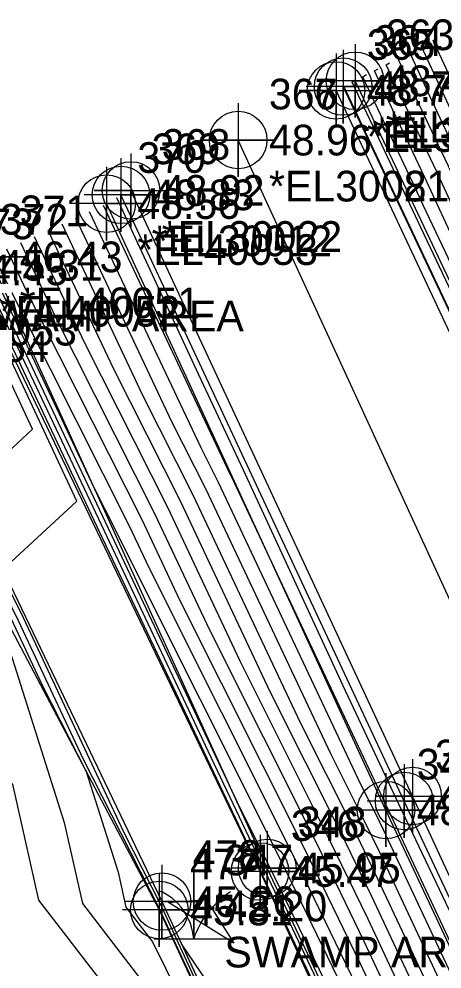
# Model space of a CAD drawing. Extents: x 2090860 to 2091277, y 159470 to 160080.
# Drawn here: x 2090910.5 to 2090944.9, y 159984.2 to 160061.6 of the extents above; entities that cross this region are included whole.
import ezdxf

# ---------------------------------------------------------------- set-up
doc = ezdxf.new("R2010")
doc.units = 0
for name, color, linetype in [('DTM Contours Major', 7, 'Continuous'), ('DTM Contours Minor', 7, 'Continuous'), ('Exist DTM Breakline', 7, 'Continuous'), ('Exist DTM Breakline Cogo Comment', 7, 'Continuous'), ('Exist DTM Breakline Cogo Elevation', 7, 'Continuous'), ('Exist DTM Breakline Cogo Number', 7, 'Continuous'), ('Exist DTM Breakline Cogo Point CELL', 7, 'Continuous'), ('Exist DTM Crownline', 7, 'Continuous'), ('Exist DTM Crownline Cogo Comment', 7, 'Continuous'), ('Exist DTM Crownline Cogo Elevation', 7, 'Continuous'), ('Exist DTM Crownline Cogo Number', 7, 'Continuous'), ('Exist DTM Crownline Cogo Point CELL', 7, 'Continuous'), ('Exist Hydro Swamp or Marsh', 7, 'Continuous'), ('Exist Hydro Swamp or Marsh Cogo Comment', 7, 'Continuous'), ('Exist Hydro Swamp or Marsh Cogo Elevation', 7, 'Continuous'), ('Exist Hydro Swamp or Marsh Cogo Number', 7, 'Continuous'), ('Exist Roads EOP', 7, 'Continuous'), ('Exist Roads EOP Cogo Comment', 7, 'Continuous'), ('Exist Roads EOP Cogo Elevation', 7, 'Continuous'), ('Exist Roads EOP Cogo Number', 7, 'Continuous'), ('Exist Roads EOP Cogo Point CELL', 7, 'Continuous'), ('Exist Roads EOT', 7, 'Continuous'), ('Exist Roads EOT Cogo Comment', 7, 'Continuous'), ('Exist Roads EOT Cogo Elevation', 7, 'Continuous'), ('Exist Roads EOT Cogo Number', 7, 'Continuous'), ('Exist Roads EOT Cogo Point CELL', 7, 'Continuous')]:
    doc.layers.add(name, color=color, linetype=linetype)

msp = doc.modelspace()

# ---------------------------------------------------------------- linework, layer by layer
at = {"layer": 'DTM Contours Major'}
for points in [[(2091021.18, 159890.907), (2091013.639, 159907.174), (2091008.516, 159918.108), (2091005.725, 159924.066), (2091001.855, 159932.408), (2090996.755, 159943.477), (2090989.564, 159959.773), (2090985.428, 159962.142), (2090982.708, 159967.911), (2090974.675, 159984.898), (2090972.744, 159996.202), (2090967.23, 160007.833), (2090960.061, 160023.383), (2090954.323, 160035.484), (2090947.368, 160050.56), (2090945.472, 160054.558), (2090943.253, 160059.365), (2090943.413, 160059.46)], [(2091015.949, 159893.794), (2091005.233, 159916.667), (2090999.394, 159929.129), (2090998.605, 159930.829), (2090988.204, 159953.404), (2090986.126, 159958.114), (2090984.93, 159958.799), (2090981.087, 159966.952), (2090969.734, 159990.958), (2090969.141, 159994.43), (2090958.495, 160016.884), (2090956.34, 160021.56), (2090945.578, 160044.255), (2090943.533, 160048.687), (2090940.07, 160055.988), (2090939.423, 160057.391), (2090939.712, 160057.563)], [(2090915.092, 160045.426), (2090922.919, 160028.827), (2090925.677, 160023.356), (2090935.836, 160001.778), (2090938.587, 159996.284), (2090939.794, 159993.785), (2090945.294, 159982.053), (2090947.597, 159977.284), (2090958.084, 159954.914), (2090958.856, 159953.218), (2090962.481, 159945.429), (2090964.802, 159940.332), (2090975.096, 159918.212), (2090976.136, 159916.102), (2090980.927, 159905.726), (2090983.402, 159900.704)], [(2090910.606, 160043.392), (2090913.448, 160037.366), (2090921.532, 160021.331), (2090926.001, 160011.839), (2090934.731, 159994.403), (2090938.563, 159986.471), (2090941.418, 159980.382), (2090948.738, 159965.223), (2090954.329, 159953.296), (2090956.792, 159947.89), (2090958.683, 159943.825), (2090966.198, 159927.322), (2090971.199, 159916.575), (2090974.729, 159909.419), (2090977.08, 159904.325)], [(2090907.426, 160041.969), (2090911.786, 160032.768), (2090917.984, 160019.602), (2090928.464, 159997.339), (2090930.876, 159992.521), (2090937.332, 159979.157), (2090937.542, 159978.71), (2090949.879, 159953.162), (2090950.574, 159951.679), (2090954.727, 159942.562), (2090954.886, 159942.222), (2090962.638, 159925.196), (2090966.571, 159916.855), (2090967.464, 159914.985), (2090973.015, 159903.605)], [(2090900.828, 160040.593), (2090907.904, 160024.765), (2090911.605, 160028.202), (2090905.415, 160041.412)], [(2090878.864, 160034.967), (2090897.091, 160039.466), (2090903.651, 160025.321), (2090910.038, 160012.34), (2090912.377, 160007.335), (2090915.967, 160000.292), (2090918.562, 159992.105), (2090919.202, 159989.241), (2090921.362, 159986.426), (2090931.819, 159965.183), (2090930.712, 159963.948), (2090932.018, 159960.802), (2090932.724, 159957.106), (2090937.257, 159949.444), (2090930, 159941.72), (2090927.457, 159942.543), (2090920, 159946.378), (2090916.149, 159943.851), (2090910, 159943.546), (2090902.359, 159947.641), (2090900, 159946.671), (2090893.58, 159946.42), (2090892.56, 159944.88)]]:
    msp.add_lwpolyline(points, dxfattribs=at)
at = {"layer": 'DTM Contours Minor'}
for points in [[(2091021.989, 159891.262), (2091013.061, 159910.519), (2091009.337, 159918.469), (2091007.307, 159922.8), (2091002.667, 159932.803), (2090998.893, 159940.995), (2090990.424, 159960.188), (2090985.552, 159962.978), (2090983.114, 159968.151), (2090975.91, 159983.383), (2090973.645, 159996.645), (2090969.414, 160005.57), (2090960.992, 160023.839), (2090956.509, 160033.292), (2090948.326, 160051.028), (2090946.822, 160054.2), (2090944.211, 160059.859), (2090944.338, 160059.934)], [(2091014.217, 159903.829), (2091007.695, 159917.748), (2091004.142, 159925.332), (2091001.042, 159932.013), (2090994.617, 159945.959), (2090988.704, 159959.359), (2090985.303, 159961.306), (2090982.303, 159967.671), (2090973.44, 159986.413), (2090971.844, 159995.759), (2090965.046, 160010.096), (2090959.131, 160022.927), (2090952.137, 160037.677), (2090946.409, 160050.092), (2090944.121, 160054.915), (2090942.296, 160058.872), (2090942.487, 160058.986)], [(2091014.794, 159900.484), (2091006.874, 159917.387), (2091002.559, 159926.597), (2091000.23, 159931.619), (2090992.479, 159948.441), (2090987.845, 159958.944), (2090985.179, 159960.47), (2090981.898, 159967.432), (2090972.204, 159987.928), (2090970.943, 159995.316), (2090962.863, 160012.359), (2090958.2, 160022.472), (2090949.95, 160039.87), (2090945.45, 160049.623), (2090942.771, 160055.273), (2090941.338, 160058.378), (2090941.562, 160058.512)], [(2091015.372, 159897.139), (2091006.054, 159917.027), (2091000.976, 159927.863), (2090999.417, 159931.224), (2090990.342, 159950.923), (2090986.985, 159958.529), (2090985.054, 159959.635), (2090981.492, 159967.192), (2090970.969, 159989.443), (2090970.042, 159994.873), (2090960.679, 160014.622), (2090957.27, 160022.016), (2090947.764, 160042.063), (2090944.492, 160049.155), (2090941.421, 160055.631), (2090940.381, 160057.885), (2090940.637, 160058.037)], [(2091016.527, 159890.449), (2091004.412, 159916.306), (2090997.811, 159930.395), (2090997.792, 159930.434), (2090986.066, 159955.886), (2090985.266, 159957.699), (2090984.806, 159957.963), (2090980.682, 159966.713), (2090968.499, 159992.473), (2090968.24, 159993.988), (2090956.311, 160019.147), (2090955.409, 160021.104), (2090943.391, 160046.448), (2090942.575, 160048.218), (2090938.72, 160056.346), (2090938.465, 160056.898), (2090938.787, 160057.089)], [(2091015.092, 159888.281), (2091005.494, 159908.792), (2091002.253, 159915.399), (2090998.196, 159923.671), (2090995.587, 159929.309), (2090993.655, 159934.254), (2090987.577, 159947.689), (2090983.614, 159956.284), (2090983.391, 159956.773), (2090979.397, 159965.44), (2090979.189, 159965.897), (2090967.415, 159991.324), (2090966.567, 159993.113), (2090960.639, 160005.911), (2090959.796, 160007.69), (2090947.752, 160033.198), (2090947.057, 160034.665), (2090937.109, 160055.735), (2090936.921, 160056.131), (2090936.936, 160056.14)], [(2091009.719, 159902.684), (2091003.488, 159915.918), (2091000.285, 159922.734), (2090996.873, 159929.981), (2090990.78, 159943.197), (2090984.364, 159957.258), (2090983.277, 159959.617), (2090980.176, 159966.423), (2090978.448, 159970.155), (2090967.363, 159993.547), (2090966.269, 159995.909), (2090955.847, 160017.91), (2090953.21, 160023.496), (2090943.221, 160044.585), (2090940.726, 160049.87), (2090937.604, 160056.462), (2090937.861, 160056.615)], [(2090918.443, 160047.072), (2090925.071, 160032.691), (2090928.75, 160024.871), (2090936.833, 160007.361), (2090941.384, 159997.661), (2090946.344, 159987.242), (2090948.128, 159983.436), (2090958.851, 159960.931), (2090960.998, 159956.352), (2090964.881, 159948.099), (2090965.492, 159946.787), (2090977.739, 159920.762), (2090978.261, 159919.644), (2090983.592, 159908.064), (2090984.057, 159907.047), (2090994.33, 159884.723)], [(2090916.214, 160045.934), (2090925.287, 160026.693), (2090926.714, 160023.863), (2090938.295, 159999.263), (2090939.55, 159996.755), (2090940.102, 159995.614), (2090946.263, 159982.47), (2090947.312, 159980.299), (2090959.023, 159955.318), (2090959.373, 159954.55), (2090963.43, 159945.83), (2090964.452, 159943.584), (2090976.07, 159918.621), (2090976.488, 159917.773), (2090981.889, 159906.077), (2090983.02, 159903.782)], [(2090917.335, 160046.443), (2090927.654, 160024.558), (2090927.75, 160024.369), (2090931.7, 160015.979), (2090940.501, 159997.22), (2090941.185, 159995.783), (2090947.222, 159982.907), (2090948.733, 159979.736), (2090959.976, 159955.756), (2090960.546, 159954.544), (2090964.408, 159946.258), (2090966.553, 159941.699), (2090977.104, 159919.081), (2090978.421, 159916.221), (2090982.884, 159906.464), (2090984.288, 159903.411)], [(2090912.849, 160044.409), (2090918.183, 160033.097), (2090923.605, 160022.344), (2090930.919, 160006.809), (2090936.659, 159995.344), (2090939.178, 159990.128), (2090943.356, 159981.217), (2090948.168, 159971.253), (2090956.207, 159954.105), (2090957.824, 159950.554), (2090960.582, 159944.627), (2090965.5, 159933.827), (2090973.148, 159917.393), (2090975.433, 159912.761), (2090979.004, 159905.026)], [(2090913.971, 160044.918), (2090920.551, 160030.962), (2090924.641, 160022.85), (2090933.377, 160004.293), (2090937.623, 159995.814), (2090939.486, 159991.957), (2090944.325, 159981.635), (2090947.882, 159974.268), (2090957.145, 159954.509), (2090958.34, 159951.886), (2090961.531, 159945.028), (2090965.151, 159937.08), (2090974.122, 159917.803), (2090975.785, 159914.432), (2090979.965, 159905.376)], [(2090911.728, 160043.901), (2090915.815, 160035.231), (2090922.569, 160021.838), (2090928.46, 160009.324), (2090935.695, 159994.873), (2090938.871, 159988.3), (2090942.387, 159980.799), (2090948.453, 159968.238), (2090955.268, 159953.701), (2090957.308, 159949.222), (2090959.632, 159944.226), (2090965.849, 159930.575), (2090972.174, 159916.984), (2090975.081, 159911.09), (2090978.042, 159904.675)], [(2090909.485, 160042.884), (2090911.08, 160039.501), (2090920.496, 160020.825), (2090923.543, 160014.354), (2090933.768, 159993.933), (2090938.255, 159984.643), (2090940.449, 159979.964), (2090949.023, 159962.207), (2090953.39, 159952.892), (2090956.276, 159946.558), (2090957.734, 159943.424), (2090966.547, 159924.07), (2090970.225, 159916.166), (2090974.377, 159907.749), (2090976.119, 159903.975)], [(2090907.788, 160042.123), (2090909.613, 160038.271), (2090916.596, 160023.437), (2090918.424, 160019.813), (2090918.625, 160019.385), (2090931.84, 159992.992), (2090937.64, 159980.985), (2090938.511, 159979.128), (2090949.594, 159956.177), (2090951.513, 159952.083), (2090955.244, 159943.894), (2090955.835, 159942.622), (2090967.245, 159917.565), (2090968.277, 159915.347), (2090973.673, 159904.407)], [(2090908.363, 160042.375), (2090908.712, 160041.635), (2090919.46, 160020.319), (2090921.084, 160016.87), (2090932.804, 159993.462), (2090937.948, 159982.814), (2090939.48, 159979.546), (2090949.308, 159959.192), (2090952.452, 159952.487), (2090955.76, 159945.226), (2090956.784, 159943.023), (2090966.896, 159920.817), (2090969.251, 159915.756), (2090974.025, 159906.078), (2090975.157, 159903.624)], [(2090899.563, 160040.331), (2090909.838, 160017.348), (2090915.213, 160022.339), (2090906.225, 160041.521)], [(2090906.701, 160041.663), (2090916.132, 160021.763), (2090917.301, 160019.278), (2090919.911, 160013.734), (2090930.148, 159992.169), (2090935.256, 159981.379), (2090936.616, 159978.521), (2090944.254, 159962.401), (2090949.505, 159951.363), (2090952.287, 159945.521), (2090954.079, 159941.72), (2090957.972, 159933.464), (2090966.981, 159914.593), (2090968.004, 159912.496), (2090972.898, 159902.775)], [(2090907.064, 160041.816), (2090913.959, 160027.266), (2090917.643, 160019.44), (2090925.862, 160001.979), (2090930.45, 159992.315), (2090932.739, 159987.48), (2090936.984, 159978.555), (2090940.085, 159972.01), (2090949.879, 159951.423), (2090950.719, 159949.661), (2090954.36, 159941.937), (2090962.272, 159925.16), (2090967.223, 159914.789), (2090970.51, 159908.05), (2090973.119, 159902.868)], [(2090889.626, 160037.801), (2090897.613, 160039.773), (2090906.696, 160020.187), (2090910.431, 160012.597), (2090915.684, 160001.354), (2090921.934, 159989.091), (2090923.078, 159986.602), (2090934.563, 159961.929)], [(2090898.298, 160040.07), (2090902.561, 160030.534), (2090909.741, 160015.052), (2090910.823, 160012.853), (2090918.991, 159995.373), (2090922.033, 159989.405), (2090928.025, 159976.37), (2090934.637, 159962.164), (2090937.707, 159955.499), (2090940.625, 159949.227), (2090948.523, 159931.794), (2090953.056, 159921.956), (2090965.045, 159895.337)], [(2090918.502, 159981.498), (2090912.109, 159989.826), (2090910, 159999.276), (2090908.566, 160000), (2090909.867, 160000.133), (2090907.218, 160011.584), (2090906.209, 160014.977), (2090900.403, 160029.812), (2090897.561, 160035.589), (2090896.047, 160038.853), (2090870.427, 160032.529), (2090884.177, 160034.776), (2090874.349, 160030), (2090870.467, 160020.467), (2090870.195, 160020), (2090870, 160019.313), (2090862.368, 160017.632), (2090862.193, 160015.615)], [(2090868.102, 160032.133), (2090896.569, 160039.16), (2090900.606, 160030.455), (2090908.186, 160015.051), (2090909.143, 160012.603), (2090909.31, 160012.043), (2090909.771, 160010.051), (2090914.18, 159996.146), (2090915.655, 159989.533), (2090920.643, 159983.036), (2090925.583, 159973.001), (2090921.92, 159968.915), (2090922.513, 159967.487), (2090920, 159968.451), (2090915.329, 159970), (2090910, 159971.335), (2090905.305, 159974.695), (2090900, 159975.694), (2090891.754, 159970), (2090890, 159969.104), (2090886.285, 159967.429), (2090886.339, 159960.983), (2090883.674, 159965.814)], [(2090922.651, 159989.628), (2090925.734, 159989.867), (2090927.977, 159986.319), (2090922.651, 159989.628)], [(2090971.838, 159903.298), (2090965.559, 159913.825), (2090960.005, 159918.329), (2090953.785, 159940.417), (2090952.656, 159942.311), (2090953.018, 159943.141), (2090949.131, 159951.303), (2090948.423, 159952.793), (2090946.196, 159957.493), (2090935.425, 159968.942), (2090923.729, 159986.244), (2090932.971, 159966.138), (2090934.711, 159962.399), (2090939.74, 159951.48), (2090940.783, 159949.239), (2090943.605, 159943.01), (2090953.294, 159921.983), (2090957.425, 159912.812), (2090965.766, 159894.719)]]:
    msp.add_lwpolyline(points, dxfattribs=at)
at = {"layer": 'Exist DTM Breakline'}
for points in [[(2091054.851, 159814.302), (2091016.781, 159888.977), (2090997.773, 159930.425), (2090980.346, 159966.514), (2090937.845, 160056.578)], [(2091012.481, 159842.709), (2090995.611, 159879.293), (2090976.725, 159918.896), (2090959.8, 159955.653), (2090940.36, 159997.15), (2090917.627, 160046.575)], [(2091019.809, 159801.913), (2091004.418, 159836.946), (2090986.475, 159875.987), (2090967.517, 159915.028), (2090950.041, 159951.449), (2090930.695, 159992.433), (2090908.049, 160042.233)], [(2091019.111, 159801.55), (2091003.076, 159836.513), (2090986.016, 159875.809), (2090966.872, 159914.505), (2090949.073, 159951.294), (2090930.109, 159992.15), (2090906.432, 160041.549)], [(2090898.02, 160040.012), (2090922.126, 159989.703), (2090940.871, 159949.246), (2090967.299, 159891.857)], [(2090895.734, 160038.669), (2090921.911, 159989.017), (2090940.353, 159949.207), (2090966.689, 159891.716)]]:
    msp.add_lwpolyline(points, dxfattribs=at)
at = {"layer": 'Exist DTM Breakline Cogo Point CELL'}
for points in [[(2090937.845, 160059.578), (2090937.845, 160053.578), (2090937.845, 160056.578), (2090940.845, 160056.578), (2090934.845, 160056.578)], [(2090917.627, 160049.575), (2090917.627, 160043.575), (2090917.627, 160046.575), (2090920.627, 160046.575), (2090914.627, 160046.575)], [(2090908.049, 160045.233), (2090908.049, 160039.233), (2090908.049, 160042.233), (2090911.049, 160042.233), (2090905.049, 160042.233)], [(2090940.36, 160000.15), (2090940.36, 159994.15), (2090940.36, 159997.15), (2090943.36, 159997.15), (2090937.36, 159997.15)], [(2090930.109, 159995.15), (2090930.109, 159989.15), (2090930.109, 159992.15), (2090933.109, 159992.15), (2090927.109, 159992.15)], [(2090930.695, 159995.433), (2090930.695, 159989.433), (2090930.695, 159992.433), (2090933.695, 159992.433), (2090927.695, 159992.433)], [(2090922.126, 159992.703), (2090922.126, 159986.703), (2090922.126, 159989.703), (2090925.126, 159989.703), (2090919.126, 159989.703)], [(2090921.911, 159992.017), (2090921.911, 159986.017), (2090921.911, 159989.017), (2090924.911, 159989.017), (2090918.911, 159989.017)]]:
    msp.add_lwpolyline(points, dxfattribs=at)
for centre in [(2090937.845, 160056.578), (2090917.627, 160046.575), (2090940.36, 159997.15), (2090930.695, 159992.433), (2090930.109, 159992.15), (2090922.126, 159989.703), (2090921.911, 159989.017)]:
    msp.add_circle(centre, 2.344, dxfattribs=at)
at = {"layer": 'Exist DTM Crownline'}
msp.add_lwpolyline([(2091041.896, 159807.58), (2091022.738, 159848.476), (2091006.16, 159884.052), (2090987.202, 159924.29), (2090970.349, 159960.929), (2090951.234, 160001.943), (2090928.333, 160051.748)], dxfattribs=at)
at = {"layer": 'Exist DTM Crownline Cogo Point CELL'}
msp.add_lwpolyline([(2090928.333, 160054.748), (2090928.333, 160048.748), (2090928.333, 160051.748), (2090931.333, 160051.748), (2090925.333, 160051.748)], dxfattribs=at)
msp.add_circle((2090928.333, 160051.748), 2.344, dxfattribs=at)
at = {"layer": 'Exist Hydro Swamp or Marsh'}
msp.add_line((2090924.711, 159989.333), (2090924.711, 159989.333), dxfattribs=at)
msp.add_lwpolyline([(2090921.486, 159986.659), (2090924.712, 159986.659), (2090924.712, 159992.576), (2090924.712, 159986.659), (2090927.937, 159986.659)], dxfattribs=at)
for centre, radius, start, end in [((2090920.112, 159986.326), 4.612, 4.14034, 67.53497), ((2090931.553, 159984.386), 7.208, 122.12745, 161.62219)]:
    msp.add_arc(centre, radius, start, end, dxfattribs=at)
at = {"layer": 'Exist Roads EOP'}
for points in [[(2091050.887, 159811.953), (2091031.567, 159853.358), (2091015.44, 159888.433), (2090996.018, 159929.558), (2090979.118, 159965.859), (2090960.144, 160006.791), (2090936.877, 160056.11)], [(2091032.873, 159803.467), (2091013.956, 159843.468), (2090996.901, 159879.939), (2090978.321, 159919.673), (2090961.239, 159956.493), (2090941.84, 159997.888), (2090918.792, 160047.284)]]:
    msp.add_lwpolyline(points, dxfattribs=at)
at = {"layer": 'Exist Roads EOP Cogo Point CELL'}
for points in [[(2090936.877, 160059.11), (2090936.877, 160053.11), (2090936.877, 160056.11), (2090939.877, 160056.11), (2090933.877, 160056.11)], [(2090918.792, 160050.284), (2090918.792, 160044.284), (2090918.792, 160047.284), (2090921.792, 160047.284), (2090915.792, 160047.284)], [(2090941.84, 160000.888), (2090941.84, 159994.888), (2090941.84, 159997.888), (2090944.84, 159997.888), (2090938.84, 159997.888)]]:
    msp.add_lwpolyline(points, dxfattribs=at)
for centre in [(2090936.877, 160056.11), (2090918.792, 160047.284), (2090941.84, 159997.888)]:
    msp.add_circle(centre, 2.344, dxfattribs=at)
at = {"layer": 'Exist Roads EOT'}
for points in [[(2091050.358, 159811.619), (2091030.997, 159852.885), (2091014.318, 159887.944), (2090995.228, 159929.102), (2090978.274, 159965.509), (2090959.414, 160006.451), (2090936.296, 160055.791)], [(2091033.429, 159803.706), (2091014.624, 159843.758), (2090997.608, 159880.208), (2090978.895, 159919.952), (2090961.789, 159956.632), (2090942.516, 159998.302), (2090919.608, 160047.643)]]:
    msp.add_lwpolyline(points, dxfattribs=at)
at = {"layer": 'Exist Roads EOT Cogo Point CELL'}
for points in [[(2090936.296, 160058.791), (2090936.296, 160052.791), (2090936.296, 160055.791), (2090933.296, 160055.791), (2090939.296, 160055.791)], [(2090928.333, 160054.748), (2090928.333, 160048.748), (2090928.333, 160051.748), (2090925.333, 160051.748), (2090931.333, 160051.748)], [(2090919.608, 160050.643), (2090919.608, 160044.643), (2090919.608, 160047.643), (2090916.608, 160047.643), (2090922.608, 160047.643)], [(2090942.516, 160001.302), (2090942.516, 159995.302), (2090942.516, 159998.302), (2090939.516, 159998.302), (2090945.516, 159998.302)]]:
    msp.add_lwpolyline(points, dxfattribs=at)
for centre in [(2090936.296, 160055.791), (2090928.333, 160051.748), (2090919.608, 160047.643), (2090942.516, 159998.302)]:
    msp.add_circle(centre, 2.344, dxfattribs=at)

# ---------------------------------------------------------------- texts
at = {"layer": 'Exist DTM Breakline Cogo Comment'}
for s, p in [('*EL40054', (2090940.345, 160051.578)), ('*EL40053', (2090920.127, 160041.575)), ('*EL40051', (2090910.549, 160037.233)), ('*EL40052', (2090908.932, 160036.549)), ('*BL40053', (2090900.52, 160035.012)), ('*BL40054', (2090898.234, 160033.669))]:
    msp.add_text(s, height=2.5, dxfattribs=at).set_placement(p)
at = {"layer": 'Exist DTM Breakline Cogo Elevation'}
for s, p in [('48.41', (2090940.345, 160055.328)), ('48.56', (2090920.127, 160045.325)), ('46.43', (2090910.549, 160040.983)), ('45.31', (2090908.932, 160040.299)), ('48.46', (2090942.86, 159995.9)), ('45.47', (2090932.609, 159990.9)), ('45.95', (2090933.195, 159991.183)), ('45.26', (2090924.626, 159988.453)), ('45.81', (2090924.411, 159987.767))]:
    msp.add_text(s, height=2.5, dxfattribs=at).set_placement(p)
at = {"layer": 'Exist DTM Breakline Cogo Number'}
for s, p in [('363', (2090940.345, 160059.078)), ('370', (2090920.127, 160049.075)), ('372', (2090908.932, 160044.049)), ('371', (2090910.549, 160044.733)), ('349', (2090942.86, 159999.65)), ('346', (2090932.609, 159994.65)), ('348', (2090933.195, 159994.933)), ('478', (2090924.626, 159992.203)), ('477', (2090924.411, 159991.517))]:
    msp.add_text(s, height=2.5, dxfattribs=at).set_placement(p)
at = {"layer": 'Exist DTM Crownline Cogo Comment'}
msp.add_text('*EL30081', height=2.5, dxfattribs=at).set_placement((2090930.833, 160046.748))
at = {"layer": 'Exist DTM Crownline Cogo Elevation'}
msp.add_text('48.96', height=2.5, dxfattribs=at).set_placement((2090930.833, 160050.498))
at = {"layer": 'Exist DTM Crownline Cogo Number'}
msp.add_text('367', height=2.5, dxfattribs=at).set_placement((2090930.833, 160054.248))
at = {"layer": 'Exist Hydro Swamp or Marsh Cogo Comment'}
for p in [(2090906.125, 160036.171), (2090927.211, 159984.333)]:
    msp.add_text('SWAMP AREA', height=2.5, dxfattribs=at).set_placement(p)
at = {"layer": 'Exist Hydro Swamp or Marsh Cogo Elevation'}
for s, p in [('44.45', (2090906.125, 160039.921)), ('45.20', (2090927.211, 159988.083))]:
    msp.add_text(s, height=2.5, dxfattribs=at).set_placement(p)
at = {"layer": 'Exist Hydro Swamp or Marsh Cogo Number'}
for s, p in [('373', (2090906.125, 160043.671)), ('347', (2090927.211, 159991.833))]:
    msp.add_text(s, height=2.5, dxfattribs=at).set_placement(p)
at = {"layer": 'Exist Roads EOP Cogo Comment'}
for s, p in [('*EL30011', (2090939.377, 160051.11)), ('*EL30012', (2090921.292, 160042.284))]:
    msp.add_text(s, height=2.5, dxfattribs=at).set_placement(p)
at = {"layer": 'Exist Roads EOP Cogo Elevation'}
for s, p in [('48.77', (2090939.377, 160054.86)), ('48.83', (2090921.292, 160046.034)), ('48.88', (2090944.34, 159996.638))]:
    msp.add_text(s, height=2.5, dxfattribs=at).set_placement(p)
at = {"layer": 'Exist Roads EOP Cogo Number'}
for s, p in [('364', (2090939.377, 160058.61)), ('369', (2090921.292, 160049.784)), ('350', (2090944.34, 160000.388))]:
    msp.add_text(s, height=2.5, dxfattribs=at).set_placement(p)
at = {"layer": 'Exist Roads EOT Cogo Comment'}
for s, p in [('*EL30021', (2090938.796, 160050.791)), ('*EL30021', (2090930.833, 160046.748)), ('*EL30022', (2090922.108, 160042.643))]:
    msp.add_text(s, height=2.5, dxfattribs=at).set_placement(p)
at = {"layer": 'Exist Roads EOT Cogo Elevation'}
for s, p in [('48.79', (2090938.796, 160054.541)), ('48.96', (2090930.833, 160050.498)), ('48.92', (2090922.108, 160046.393))]:
    msp.add_text(s, height=2.5, dxfattribs=at).set_placement(p)
at = {"layer": 'Exist Roads EOT Cogo Number'}
for s, p in [('365', (2090938.796, 160058.291)), ('366', (2090930.833, 160054.248)), ('368', (2090922.108, 160050.143))]:
    msp.add_text(s, height=2.5, dxfattribs=at).set_placement(p)

doc.saveas('drawing.dxf')
